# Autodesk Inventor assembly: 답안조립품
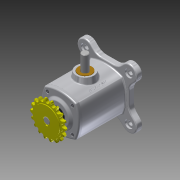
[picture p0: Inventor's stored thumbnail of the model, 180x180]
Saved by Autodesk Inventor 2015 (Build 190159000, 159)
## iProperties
Created: 2016-05
Part Number: 답안조립품
Document SubType Name: Assembly
Designer: Administrator
Author: Administrator
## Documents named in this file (11)
- C:\Users\Administrator\Desktop\460507V1003\답안조립품.iam
- C:\Users\Administrator\Desktop\460507V1003\본체.ipt
- C:\Users\Administrator\Desktop\460507V1003\편심축.ipt
- C:\Users\Administrator\Desktop\460507V1003\커버.ipt
- C:\Users\Administrator\Desktop\460507V1003\M4x0.7x12.ipt
- C:\Users\Administrator\Desktop\460507V1003\베어링-6203.ipt
- C:\Users\Administrator\Desktop\460507V1003\오일실.ipt
- C:\Users\Administrator\Desktop\460507V1003\스프로킷.ipt
- C:\Users\Administrator\Desktop\460507V1003\키5x5.ipt
- C:\Users\Administrator\Desktop\460507V1003\부시.ipt
- C:\Users\Administrator\Desktop\460507V1003\슬라이더.ipt
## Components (8 placed, 1 different names)
1. M4x0.7x12:1 — 각도:4
2. M4x0.7x12:3
3. M4x0.7x12:4
4. M4x0.7x12:5
5. M4x0.7x12:2 — 각도:3
6. M4x0.7x12:6
7. M4x0.7x12:7
8. M4x0.7x12:8
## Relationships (2: Angle 2)
- 각도:3 [Angle]: M4x0.7x12:2
- 각도:4 [Angle]: M4x0.7x12:1
